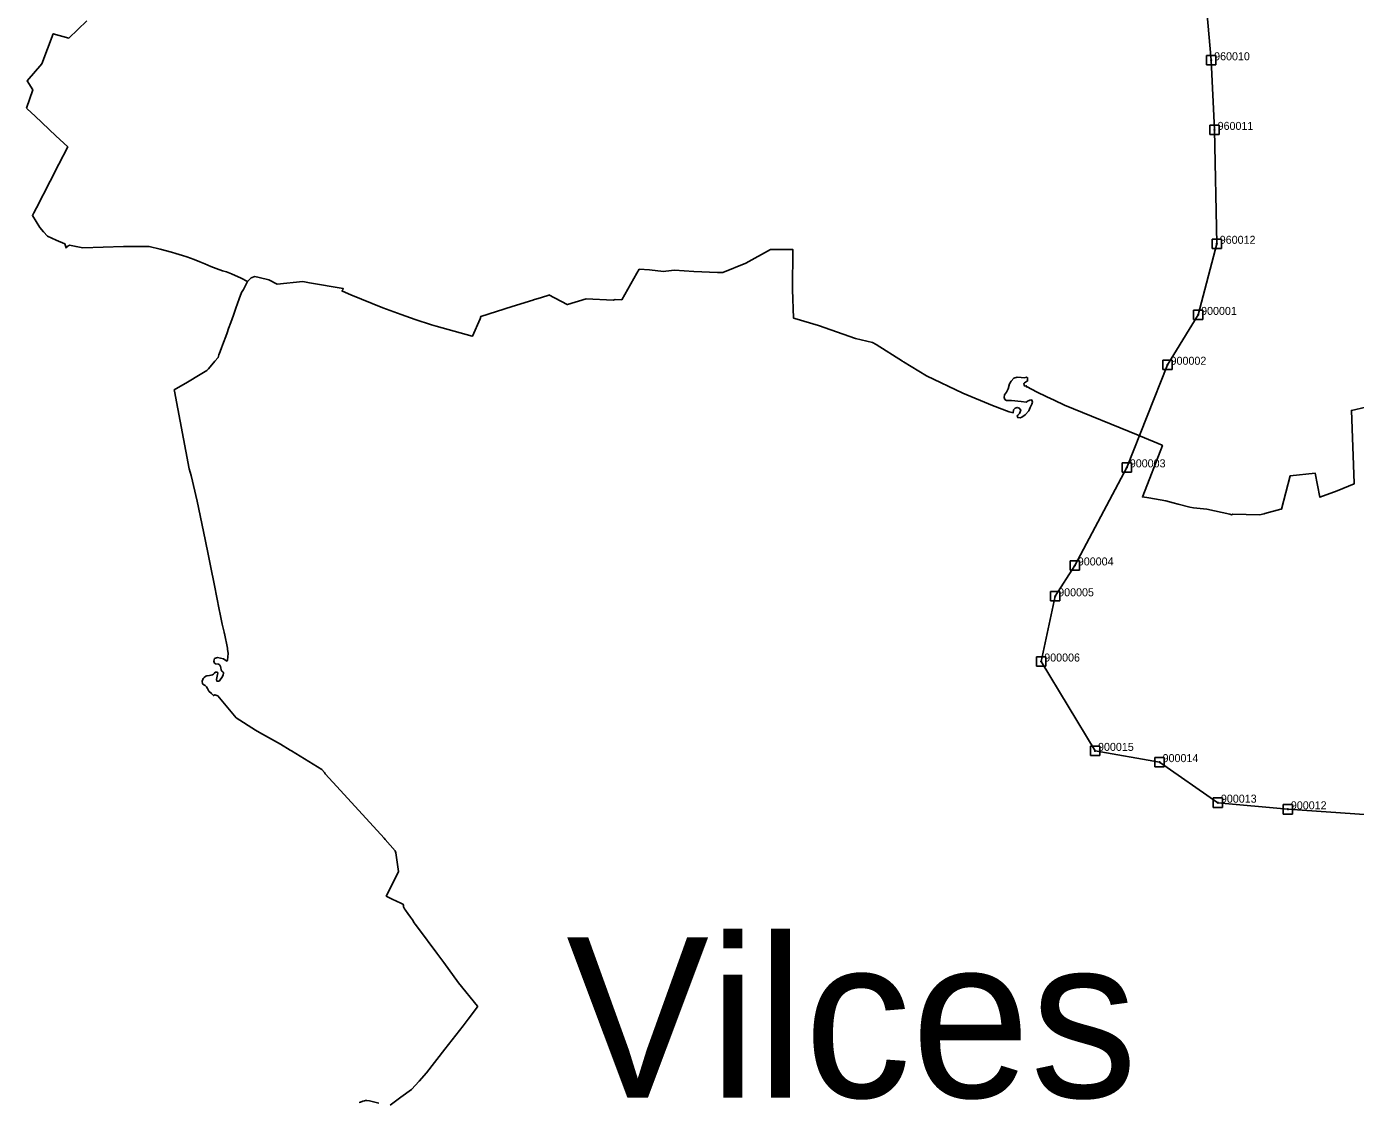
# Model space of a CAD drawing. Extents: x 462479 to 502016, y 241775 to 305873.
# Drawn here: x 464119 to 474079, y 250516 to 258575 of the extents above; entities that cross this region are included whole.
import ezdxf

# ---------------------------------------------------------------- set-up
doc = ezdxf.new("R2010")
doc.units = 0
for name, color, linetype in [('Default', 7, 'Continuous'), ('Level 19', 7, 'Continuous'), ('Level 51', 7, 'Continuous'), ('novada_robeza', 7, 'Continuous'), ('pagastu_nosaukumi', 7, 'Continuous'), ('pagastu_robezas', 7, 'Continuous')]:
    doc.layers.add(name, color=color, linetype=linetype)

msp = doc.modelspace()

# ---------------------------------------------------------------- linework, layer by layer
at = {"layer": 'Default'}
msp.add_lwpolyline([(474182.1, 252670), (473572.7, 252711.5), (473048.4, 252761.4), (472611.6, 253065.1), (472127.5, 253149.3), (471724.4, 253818.6), (471829, 254307.4), (471976, 254538.5), (472365.7, 255273.2), (472671.4, 256041.8), (472900.1, 256415), (473039.9, 256947.9), (473023.9, 257801.1), (472997.8, 258322.6), (472947.4, 258891), (472993, 259213), (473256.3, 259523.2), (473619.6, 259463), (473786.7, 259230.4), (474148.4, 259119.5)], dxfattribs=at)
at = {"layer": 'Level 19'}
for p, q in [((472962.8, 258357.6), (473032.8, 258357.6)), ((472962.8, 258287.6), (472962.8, 258357.6)), ((473032.8, 258357.6), (473032.8, 258287.6)), ((473032.8, 258287.6), (472962.8, 258287.6)), ((472988.9, 257836.1), (473058.9, 257836.1)), ((472988.9, 257766.1), (472988.9, 257836.1)), ((473058.9, 257766.1), (472988.9, 257766.1)), ((473058.9, 257836.1), (473058.9, 257766.1)), ((473004.9, 256982.9), (473074.9, 256982.9)), ((473004.9, 256912.9), (473004.9, 256982.9)), ((473074.9, 256982.9), (473074.9, 256912.9)), ((473074.9, 256912.9), (473004.9, 256912.9)), ((472865.1, 256450), (472935.1, 256450)), ((472865.1, 256380), (472865.1, 256450)), ((472935.1, 256380), (472865.1, 256380)), ((472935.1, 256450), (472935.1, 256380)), ((472636.4, 256076.8), (472706.4, 256076.8)), ((472636.4, 256006.8), (472636.4, 256076.8)), ((472706.4, 256076.8), (472706.4, 256006.8)), ((472706.4, 256006.8), (472636.4, 256006.8)), ((472330.7, 255308.2), (472400.7, 255308.2)), ((472330.7, 255238.2), (472330.7, 255308.2)), ((472330.7, 255308.2), (472400.7, 255308.2)), ((472330.7, 255238.2), (472330.7, 255308.2)), ((472400.7, 255308.2), (472400.7, 255238.2)), ((472400.7, 255308.2), (472400.7, 255238.2)), ((472400.7, 255238.2), (472330.7, 255238.2)), ((472400.7, 255238.2), (472330.7, 255238.2)), ((471941, 254573.5), (472011, 254573.5)), ((471941, 254503.5), (471941, 254573.5)), ((471941, 254573.5), (472011, 254573.5)), ((471941, 254503.5), (471941, 254573.5)), ((472011, 254573.5), (472011, 254503.5)), ((472011, 254573.5), (472011, 254503.5)), ((472011, 254503.5), (471941, 254503.5)), ((472011, 254503.5), (471941, 254503.5)), ((471794, 254342.4), (471864, 254342.4)), ((471794, 254272.4), (471794, 254342.4)), ((471864, 254272.4), (471794, 254272.4)), ((471864, 254342.4), (471864, 254272.4)), ((471689.4, 253853.6), (471759.4, 253853.6)), ((471689.4, 253783.6), (471689.4, 253853.6)), ((471759.4, 253783.6), (471689.4, 253783.6)), ((471759.4, 253853.6), (471759.4, 253783.6)), ((472092.5, 253184.3), (472162.5, 253184.3)), ((472092.5, 253114.3), (472092.5, 253184.3)), ((472162.5, 253184.3), (472162.5, 253114.3)), ((472162.5, 253114.3), (472092.5, 253114.3)), ((472576.6, 253100.1), (472646.6, 253100.1)), ((472576.6, 253030.1), (472576.6, 253100.1)), ((472646.6, 253100.1), (472646.6, 253030.1)), ((472646.6, 253030.1), (472576.6, 253030.1)), ((473013.4, 252796.4), (473083.4, 252796.4)), ((473013.4, 252726.4), (473013.4, 252796.4)), ((473083.4, 252796.4), (473083.4, 252726.4)), ((473083.4, 252726.4), (473013.4, 252726.4)), ((473537.7, 252746.5), (473607.7, 252746.5)), ((473537.7, 252676.5), (473537.7, 252746.5)), ((473607.7, 252746.5), (473607.7, 252676.5)), ((473607.7, 252676.5), (473537.7, 252676.5))]:
    msp.add_line(p, q, dxfattribs=at)
for centre in [(472997.8, 258322.5), (473023.9, 257801.1), (473039.9, 256947.9), (472900.1, 256414.9), (472671.5, 256041.8), (472365.7, 255273.2), (472365.7, 255273.2), (471976, 254538.5), (471976, 254538.5), (471829, 254307.4), (471724.5, 253818.6), (472127.5, 253149.3), (472611.7, 253065.1), (473048.4, 252761.3), (473572.8, 252711.5)]:
    msp.add_circle(centre, 3.5, dxfattribs=at)
at = {"layer": 'novada_robeza'}
for points in [[(464119.2, 257962.9), (464165.2, 258102), (464123.1, 258169.7), (464234.5, 258296.4), (464319.3, 258520.7), (464436.2, 258488.6), (464571.4, 258618.8)], [(465775.4, 256665.8), (465726.5, 256689.7), (465654.7, 256723.3), (465618.8, 256737.3), (465587.3, 256745.7), (465540.7, 256763.2), (465500.8, 256778), (465454.4, 256796.6), (465416.9, 256813.9), (465374.4, 256831), (465321.3, 256849.6), (465287.9, 256860.4), (465237, 256876.4), (465205.8, 256886.2), (465121.6, 256907), (465037.4, 256927.9), (464941.9, 256927.9), (464846.4, 256927.9), (464693.7, 256922.3), (464541.1, 256916.8), (464490.7, 256926.7), (464440.4, 256936.6), (464433.4, 256933.5), (464426.4, 256930.5), (464420.8, 256923.5), (464415.2, 256916.5), (464411.1, 256932.5), (464407, 256948.5), (464340.9, 256976.2), (464274.8, 257004), (464246.9, 257036.8), (464218.9, 257069.6), (464190.8, 257115.3), (464162.6, 257160.9), (464174, 257179.3), (464194.1, 257218.4), (464296.7, 257417.9), (464360.4, 257543.6), (464427.9, 257675.3), (464337.6, 257757), (464183.5, 257904.1), (464124.7, 257957.9), (464119.2, 257962.9)], [(465775.4, 256665.8), (465743.8, 256604.6), (465731.2, 256582.7), (465713.4, 256534.5), (465688.2, 256466), (465669.3, 256413.7), (465649.7, 256359.3), (465633, 256312.3), (465622.1, 256281.7), (465611.4, 256253.4), (465594.8, 256207.3), (465580.4, 256168.5), (465570.8, 256142), (465561.2, 256116.5), (465554.8, 256097.1), (465531.2, 256068.7), (465483.9, 256012), (465471.3, 255998.1), (465420.6, 255968.4), (465324.1, 255911.2), (465225.9, 255853.3), (465226.9, 255844.7), (465338.2, 255261.2), (465354, 255213.3), (465396.9, 255020.3), (465444.9, 254793), (465459.5, 254721.1), (465479.3, 254623.1), (465497.2, 254534.9), (465526.8, 254389.3), (465563.9, 254207.9), (465570.7, 254172.3), (465586.3, 254099), (465598.9, 254038.3), (465600.8, 254032.6), (465601.6, 254028.7), (465624.9, 253918.6), (465625.7, 253911.5), (465629.6, 253877.6), (465625.3, 253828.6), (465619.8, 253821.6), (465594, 253839.9), (465549.5, 253849.2), (465534, 253844.3), (465528.8, 253840.7), (465524.1, 253831.9), (465522, 253821.3), (465528.5, 253807.4), (465535.7, 253801.8), (465557.2, 253798.9), (465562.8, 253796.1), (465567.6, 253791.1), (465572, 253780.3), (465576, 253770.3), (465577.5, 253757.7), (465582.8, 253747.3), (465591, 253741.4), (465594.4, 253737.6), (465594.8, 253732.4), (465591.6, 253719.7), (465587.1, 253707), (465564.4, 253674.6), (465560.4, 253672), (465553.2, 253670.9), (465544.2, 253672.1), (465543.9, 253683.7), (465551.4, 253722.3), (465551.8, 253732.5), (465550.7, 253736), (465544.7, 253738.6), (465536.1, 253739.9), (465532.7, 253737.8), (465527.7, 253732.5), (465521.1, 253724.2), (465512.3, 253719.4), (465501.7, 253717.1), (465490.4, 253714.1), (465470.7, 253711.5), (465461.6, 253708), (465449.6, 253700.2), (465442.8, 253691.4), (465434.5, 253672), (465439, 253651.9), (465446.5, 253644.1), (465457.7, 253638.1), (465467, 253629.1), (465475.6, 253616.8), (465484.5, 253597.8), (465504.3, 253578.4), (465519.7, 253563.1), (465531.2, 253569.5), (465551.6, 253562.7), (465690, 253397.8), (465833.9, 253305.5), (465863.9, 253286.2), (466023.6, 253199.8), (466095.9, 253153.7), (466103.8, 253148.7), (466332.7, 253009), (466351.7, 252988.1), (466357.1, 252978), (466473.2, 252851.7), (466799.7, 252496.1), (466806.7, 252485.7), (466881.4, 252400), (466887.8, 252384.6), (466905.7, 252246.6), (466819.2, 252069.1), (466815.3, 252061.6), (466859.7, 252039.5), (466924.2, 252008), (466939.1, 252000.5), (466942.8, 251999.2), (466943.6, 251990.1), (466944.3, 251981.1), (466945.3, 251979), (466946.2, 251976.9), (466952.9, 251966.6), (466959.7, 251956.2), (466977.8, 251930.3), (466995.9, 251904.4), (467010.5, 251882.7), (467025.2, 251861.1), (467032.7, 251852.5), (467057.5, 251818.7), (467193.7, 251633.2), (467245.6, 251563.5), (467357.7, 251412.9), (467498.1, 251236.9), (467497.8, 251231.3), (467430, 251140.4), (467390.7, 251089.2), (467253.9, 250913.7), (467117.1, 250738.1), (467060.7, 250675.7), (467003.8, 250612.7), (466924.1, 250554.1), (466843.7, 250495.1)], [(466760.4, 250510.1), (466688.9, 250527.2), (466669.9, 250530), (466660, 250529.5), (466653, 250527.9), (466639.5, 250525.1), (466622.3, 250519.1), (466613.2, 250514.4)]]:
    msp.add_lwpolyline(points, dxfattribs=at)
at = {"layer": 'pagastu_robezas'}
msp.add_lwpolyline([(465775.4, 256665.8), (465802.7, 256692.9), (465829.7, 256703), (465862.4, 256695.1), (465934.7, 256677.5), (465998.3, 256646.1), (466189.8, 256664.5), (466240.4, 256656), (466491.1, 256613.9), (466488.7, 256602.2), (466482.7, 256595.4), (466486.2, 256593), (466548.4, 256564.4), (466788.6, 256468.1), (466926.5, 256418.1), (467031.9, 256379.8), (467154.7, 256340.5), (467188.3, 256329.7), (467458.5, 256255.6), (467461.3, 256254.8), (467517.7, 256386.5), (467524.7, 256404.2), (467759.7, 256479.4), (467913.8, 256526.6), (467918.7, 256528), (467978.3, 256545.1), (468032.8, 256563.3), (468033, 256564.6), (468172.1, 256493.9), (468173.5, 256493.1), (468312.3, 256535.8), (468516.9, 256526), (468530.5, 256529.7), (468580.4, 256527.3), (468692.4, 256728.8), (468710.6, 256756.7), (468787.3, 256751.9), (468891.9, 256739.7), (468910.2, 256742.1), (468975.9, 256750.7), (469120.7, 256740.9), (469297.1, 256732.7), (469337, 256733.3), (469509.5, 256803.3), (469696.1, 256906), (469861.7, 256906), (469859.9, 256605.2), (469868.2, 256389.6), (469876.6, 256388.1), (470053.7, 256337), (470331.7, 256238.9), (470458.8, 256209.2), (470485.9, 256192.4), (470684.4, 256069.1), (470689.3, 256064.9), (470693, 256062.8), (470864, 255958.9), (471137.4, 255828.3), (471358.8, 255735.9), (471484.7, 255689.6), (471503.7, 255684.7), (471514.3, 255681.9), (471516.7, 255704.6), (471529.2, 255717), (471543, 255722.6), (471559.5, 255717), (471570.6, 255700.4), (471566.4, 255689.3), (471562.3, 255676.9), (471549.9, 255664.4), (471544.3, 255657.5), (471548.5, 255646.4), (471566.4, 255645), (471578.8, 255649.2), (471603.7, 255667.2), (471631.3, 255697.7), (471642.3, 255721.2), (471653.3, 255747.5), (471657.5, 255762.7), (471654.7, 255776.6), (471645.1, 255778), (471625.7, 255771), (471611.9, 255762.7), (471573.3, 255765.5), (471501.6, 255773.8), (471462.9, 255773.8), (471450.5, 255782.1), (471446.4, 255796), (471449.1, 255815.4), (471464.3, 255837.5), (471475.3, 255861.1), (471485, 255898.4), (471498.8, 255919.2), (471518.1, 255941.4), (471544.3, 255948.3), (471574.7, 255945.5), (471595.4, 255944.1), (471616.1, 255949.7), (471621.6, 255944.1), (471621.6, 255920.6), (471613.3, 255915.1), (471599.5, 255906.8), (471594, 255902.6), (471595.4, 255888.8), (471602.3, 255881.8), (471611.9, 255884.6), (471613, 255875.2), (471617.8, 255875.2), (471688.5, 255838.2), (471766.6, 255802.2), (471820.2, 255777.4), (471899.6, 255739.6), (472451, 255513.3), (472468.6, 255506.3), (472630.2, 255438.6), (472632.2, 255437.7), (472484.7, 255057.1), (472482.2, 255051.7), (472531.5, 255044.3), (472658.3, 255021.9), (472711.8, 255007.5), (472749.7, 254997.3), (472839, 254974.1), (472866.3, 254971.1), (472964.3, 254960.1), (473138, 254921.6), (473151.2, 254916.4), (473161.2, 254923.1), (473359.2, 254917.5), (473395.4, 254925.4), (473399.5, 254926.5), (473519.1, 254961.2), (473524.6, 254959.8), (473590.5, 255210.8), (473778.1, 255229.2), (473813.2, 255049.3), (473941, 255097), (474069.7, 255150.1), (474069.5, 255154.6), (474049.3, 255699.7), (474156.1, 255723.4)], dxfattribs=at)

# ---------------------------------------------------------------- texts
at = {"layer": 'Level 51'}
for s, p in [(' 960010', (472997.8, 258322.6)), (' 960011', (473023.9, 257801.1)), (' 960012', (473039.9, 256947.9)), (' 900001', (472900.1, 256415)), (' 900002', (472671.4, 256041.8)), (' 900003', (472365.7, 255273.2)), (' 900003', (472365.7, 255273.2)), (' 900004', (471976, 254538.5)), (' 900004', (471976, 254538.5)), (' 900005', (471829, 254307.4)), (' 900006', (471724.4, 253818.6)), (' 900015', (472127.5, 253149.3)), (' 900014', (472611.6, 253065.1)), (' 900013', (473048.4, 252761.4)), (' 900012', (473572.7, 252711.5))]:
    msp.add_text(s, height=60, dxfattribs=at).set_placement(p)
at = {"layer": 'pagastu_nosaukumi'}
msp.add_text('Vilces', height=1200, dxfattribs=at).set_placement((468164.2, 250552.6))

doc.saveas('drawing.dxf')
